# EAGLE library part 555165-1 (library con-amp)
AMP connector
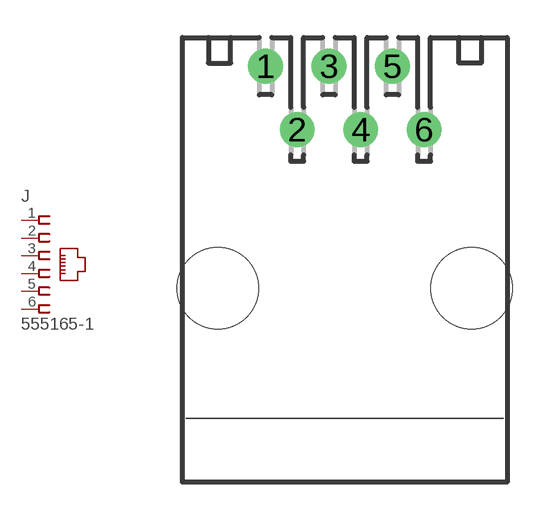
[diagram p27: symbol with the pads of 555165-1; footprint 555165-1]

Designator prefix J

## 555165-1 (MF: TYCO ELECTRONICS; MPN: 5555165-1; OC_FARNELL: 1654820; OC_NEWARK: 42K8762)  [555165-1]
1  1  pas
2  2  pas
3  3  pas
4  4  pas
5  5  pas
6  6  pas

## Footprint 555165-1 (pad centres in mm)
Modular Jack without Panel Stops
drill 0.889 round: 1 -3.175,7.747; 2 -1.905,5.207; 3 -0.635,7.747; 4 0.635,5.207; 5 1.905,7.747; 6 3.175,5.207
hole 3.251 at -5.08,-1.143
hole 3.251 at 5.08,-1.143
